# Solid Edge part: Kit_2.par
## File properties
Sűrűség: 0,000 kg/m^3
Pontosság: 0,990
Author: ahadarics
Last saved by: psaghy
Revision: 77
Username: ahadarics
Dokumentum tartalom típus: 0
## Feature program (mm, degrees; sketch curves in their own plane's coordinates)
base feature "unnamed BaseFeature 1"
sketch for "Furat_1" plane through (0, 0, -118) normal (0, 0, -1) x-axis (0, 1, 0)
  hole centre (-19, 19) bore radius 2.4585
hole "Furat_1" nominal diameter 6 finite  VBottomAngle = 118 deg; ThreadDepth = 16 mm
sketch for "unnamed Hole 1" plane through (0, 0, -118) normal (0, 0, -1) x-axis (0, 1, 0)
  hole centre (-19, -19) bore radius 2.4585
hole "unnamed Hole 1" finite
sketch for "unnamed Hole 2" plane through (0, 0, -118) normal (0, 0, -1) x-axis (0, 1, 0)
  hole centre (19, -19) bore radius 2.4585
hole "unnamed Hole 2" finite
sketch for "unnamed Hole 3" plane through (0, 0, -118) normal (0, 0, -1) x-axis (0, 1, 0)
  hole centre (19, 19) bore radius 2.4585
hole "unnamed Hole 3" finite
pattern "unnamed Pattern 1" of "Furat_1", "unnamed Hole 1", "unnamed Hole 2", "unnamed Hole 3"
sketch for "Furat_5" plane through (27.25, 0, -100.2488) normal (1, 0, 0) x-axis (0, 0, -1)
hole "Furat_5" diameter 13.157 finite  ThreadDepth = 12 mm
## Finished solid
Body 1: solid body, 374 faces, 910 edges, 588 vertices, 4 internal voids.
  Faces by surface: plane 162, cylinder 99, cone 34, torus 34, spline 30, sphere 9, swept 6
  Edges by curve: line 416, circle 282, curve on surface 186, spline 26
Bounding box of the edges (mm; curved faces can reach further): 54.500 x 54.500 x 35.000, from (-27.25, -27.25, -122) to (27.25, 27.25, -87).
Cylindrical faces by radius (mm): R0.2344 x1, R0.4113 x1, R0.4771 x1, R0.5 x7, R0.5094 x1, R0.5174 x1, R0.5226 x1, R0.5534 x1, R0.6836 x1, R0.7041 x1, R0.7049 x1, R0.7519 x1, R0.7795 x1, R0.7904 x1, R0.8051 x1, R0.824 x1, R0.8903 x1, R0.9421 x1, R0.9541 x2, R1 x12, R1.0216 x1, R1.0284 x1, R1.2857 x1, R1.5 x3, R1.75 x3, R2.4585 x8, R3 x7, R3.1 x4, R4.95 x1, R5 x6, R5.15 x4, R5.7225 x1, R7.5 x1, R8.25 x4, R8.7 x1, R10 x1, R17.5 x1, R21.3 x4, R23 x3, R27.5 x6
Conical faces (half-angle, radius in mm at the cone's reference point): 29.0546 deg R23.75 x4, 30 deg R5.1443 x1, 45 deg R2.25 x3, 45 deg R2.5 x3, 45 deg R2.75 x1, 45 deg R2.825 x1, 45 deg R3.25 x8, 45 deg R4.85 x8, 45 deg R6.72 x1, 59 deg R2.4585 x4
Toroidal faces (ring radius, tube radius in mm): R0.9686 r0.5 x1, R1.4709 r0.5007 x3, R1.6 r0.1 x3, R3.3 r0.3 x4, R4.7 r0.3 x1, R4.95 r0.2 x3, R5.65 r0.5 x4, R8.75 r0.5 x2, R9.5 r0.5 x1, R17 r0.5 x1, R18 r0.5 x1, R22 r1 x3, R26.5 r1 x6, R27.7942 r0.5 x1
Spherical faces by radius (mm): R0.5 x3, R1 x6
Planar faces by outward normal: +x 25, +y 9, +z 19, -x 6, -y 10, -z 35, oblique 58
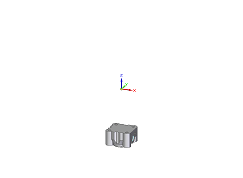
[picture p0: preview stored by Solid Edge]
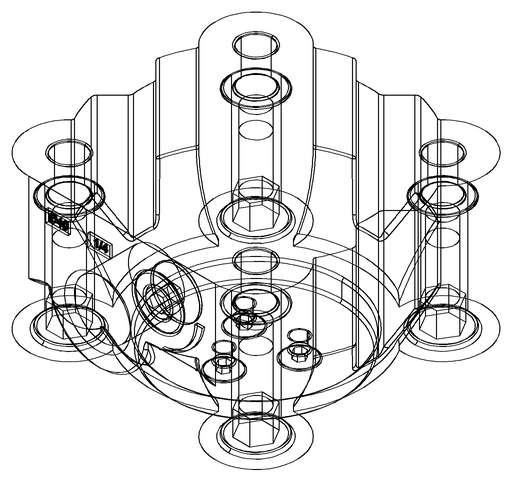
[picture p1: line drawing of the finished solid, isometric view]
